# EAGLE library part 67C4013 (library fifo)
FIFO
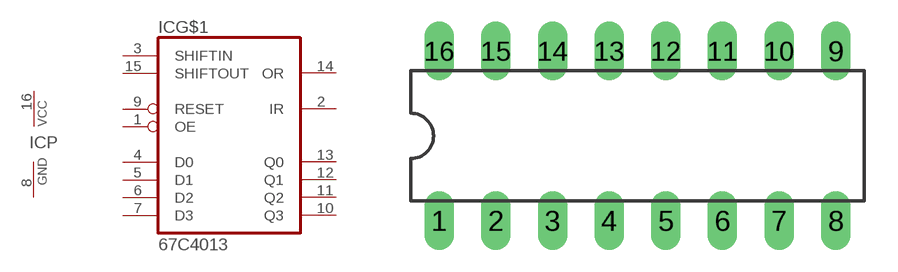
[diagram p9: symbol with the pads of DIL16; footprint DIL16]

Designator prefix IC; gates G$1=67C4013 P=PWRN

## 67C4013 (OC_FARNELL: unknown; OC_NEWARK: unknown)  [DIL16]
1  G$1:OE  in
2  G$1:IR  out
3  G$1:SHIFTIN  in
4  G$1:D0  in
5  G$1:D1  in
6  G$1:D2  in
7  G$1:D3  in
8  P:GND  pwr
9  G$1:RESET  in
10  G$1:Q3  hiz
11  G$1:Q2  hiz
12  G$1:Q1  hiz
13  G$1:Q0  hiz
14  G$1:OR  out
15  G$1:SHIFTOUT  in
16  P:VCC  pwr

## Footprint DIL16 (pad centres in mm)
Dual In Line Package
drill 0.813 long: 1 -8.89,-3.81; 2 -6.35,-3.81; 3 -3.81,-3.81; 4 -1.27,-3.81; 5 1.27,-3.81; 6 3.81,-3.81; 7 6.35,-3.81; 8 8.89,-3.81; 9 8.89,3.81; 10 6.35,3.81; 11 3.81,3.81; 12 1.27,3.81; 13 -1.27,3.81; 14 -3.81,3.81; 15 -6.35,3.81; 16 -8.89,3.81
